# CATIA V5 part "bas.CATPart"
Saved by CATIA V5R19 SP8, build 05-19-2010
Part number: Part10
Bounding box of the stored display mesh (mm): x 0 to 60, y 0 to 1280, z 0 to 600
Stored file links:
  G:\EU_thinkMotion\CFAO_2010\SIL_groupe2\SIL_groupe2\A reprendre\fnongaibaa\fnongaibaa\bas.CATPart
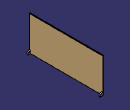
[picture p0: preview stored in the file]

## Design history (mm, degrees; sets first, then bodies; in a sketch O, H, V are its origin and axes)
Body1 (main body)
  Sketch1 on yz-plane, origin (0, 0, 0), H (0, 1, 0), V (0, 0, 1)
    line L1 (0, 0) -> (1280, 0)
    line L2 (1280, 0) -> (1280, 600)
    line L3 (1280, 600) -> (0, 600)
    line L4 (0, 600) -> (0, 0)
    length L1 = 1280
    length L4 = 600
    horizontal: L1 H, L3 H
    vertical: L2 V, L4 V
  Pad1: profile Sketch1, direction (1, 0, 0), length 10
  Sketch2 on face of Pad1 from Sketch1.L2, origin (9.4649, 1280, 378.5949), H (1, 0, 0), V (0, 0, -1)
    point P1 (-4.4649, -211.4051)
    axis line L1 (-4.4649, -60.2914) -> (-4.4649, 420)
    reference projected line E1 (0.5351, 378.5949) -> (0.5351, -21.4051) from edge [face of Pad1 from Sketch1.L2 | end face of Pad1]
    reference projected line E2 (-9.4649, 378.5949) -> (-9.4649, -21.4051) from edge [start face of Pad1 | face of Pad1 from Sketch1.L2]
    reference projected line E3 (-9.4649, -221.4051) -> (0.5351, -221.4051) from edge [face of Pad1 from Sketch1.L3 | face of Pad1 from Sketch1.L2]
    distance E3 P1 = 10
    symmetry: E1 E2 L1
    coincidence: P1 L1
  Hole1: placed by Sketch2, at (5, 1280, 590) direction (0, -1, 0), diameter 5, through (limit type 3)
  Sketch3 on end face of Pad1, origin (10, 0, 0), H (0, 1, 0), V (0, 0, 1)
    line L1 (20, 50) -> (0, 50)
    line L2 (0, 50) -> (0, 0)
    line L3 (0, 0) -> (20, 0)
    line L4 (20, 0) -> (20, 50)
    line L5 (1260, 50) -> (1280, 50)
    line L6 (1280, 50) -> (1280, 0)
    line L7 (1280, 0) -> (1260, 0)
    line L8 (1260, 0) -> (1260, 50)
    point P6 (1280, 0)
    reference projected line E1 (1280, 0) -> (1280, 530) from edge [face of Pad1 from Sketch1.L2 | end face of Pad1]
    length L3 = 20
    length L5 = 20
    length L2 = 50
    length L6 = 50
    horizontal: L1 H, L3 H, L5 H, L7 H
    vertical: L2 V, L4 V, L6 V, L8 V
    coincidence: P6 H, L6 E1
  Shaft1: profile Sketch3, axis Sketch3.L3, angle 90
  Sketch4 on face of Shaft1, origin (20.8382, 0, 25.7806), H (1, 0, 0), V (0, 0, 1)
    point P1 (4.1618, -0.7806)
    reference projected line E1 (-20.8382, -25.7806) -> (-10.8382, -25.7806) from edge [face of Shaft1 | face of Shaft1]
    reference projected line E2 (-20.8382, 504.2194) -> (-20.8382, -25.7806) from edge [start face of Pad1 | face of Shaft1]
    distance P1 E1 = 25
    distance P1 E2 = 25
  Hole2: placed by Sketch4, at (25, 0, 25) direction (0, 1, 0), diameter 5, through (limit type 3)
